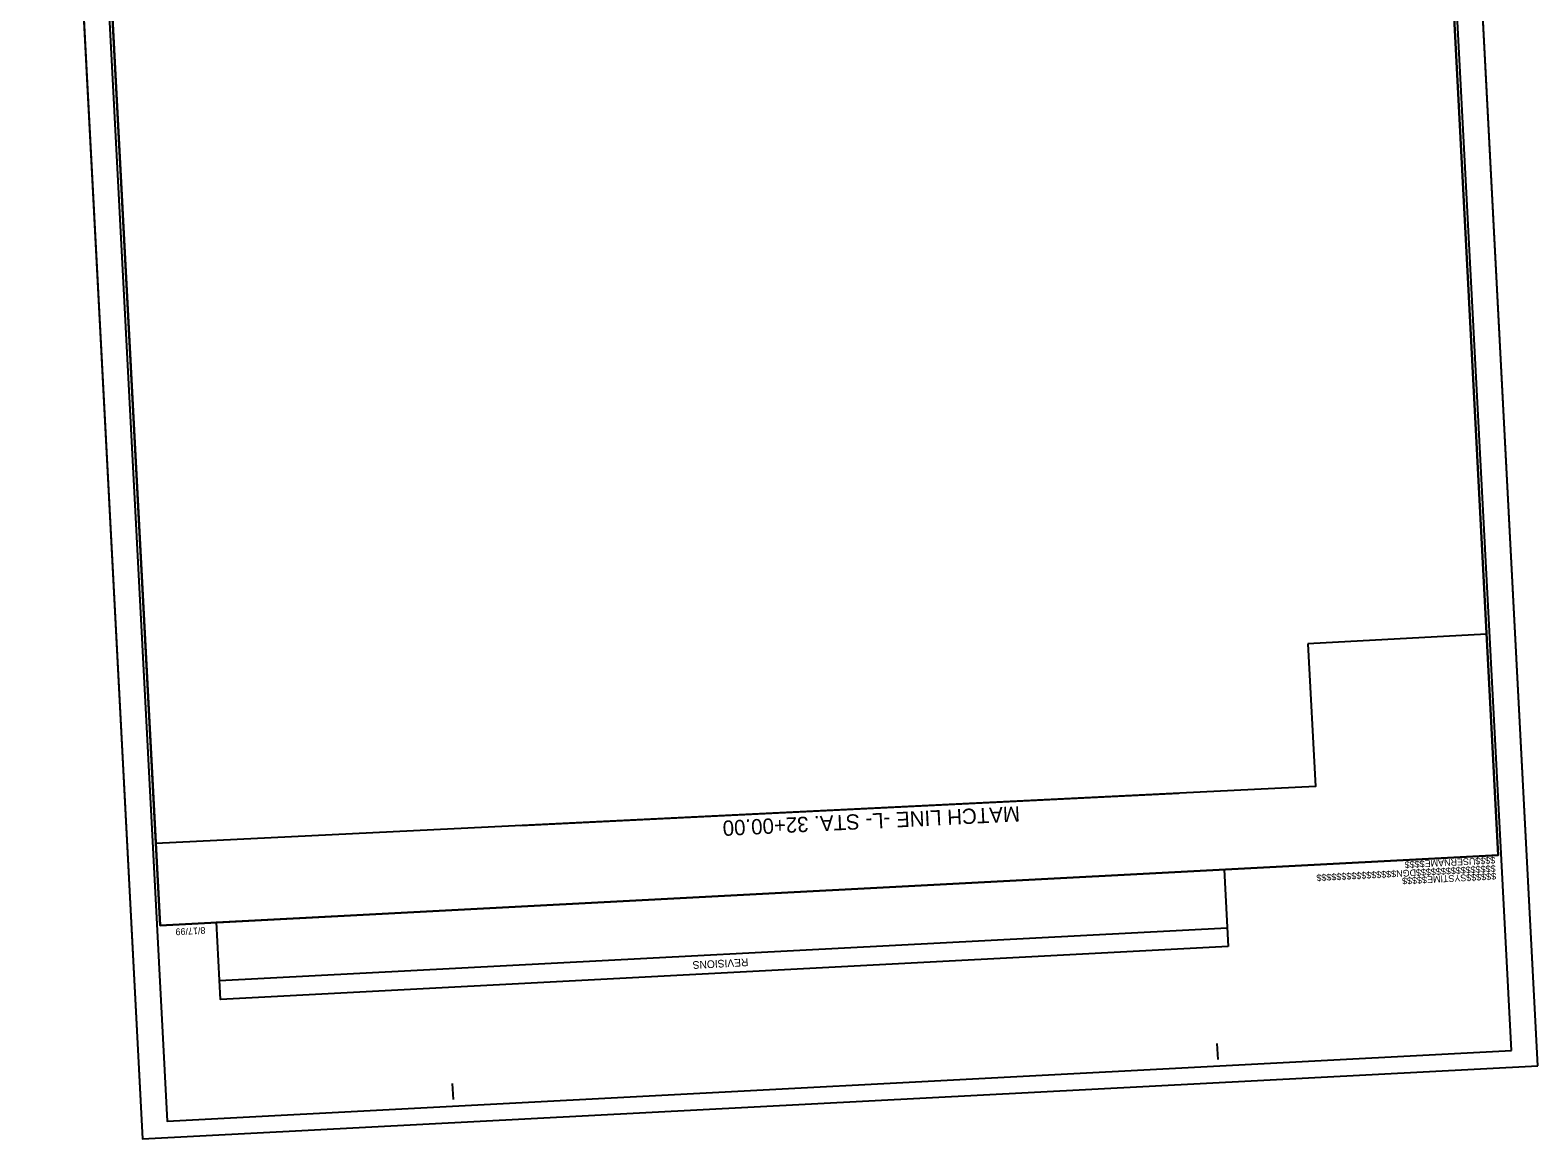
# Model space of a CAD drawing. Extents: x 2368224 to 2369406, y 803271 to 805009.
# Drawn here: x 2368224 to 2369406, y 803271 to 804140 of the extents above; entities that cross this region are included whole.
import ezdxf

# ---------------------------------------------------------------- set-up
doc = ezdxf.new("R2010")
doc.units = 0
for name, color, linetype in [('Old_Level_10', 7, 'Continuous'), ('Old_Level_15', 7, 'Continuous'), ('Old_Level_18', 7, 'Continuous'), ('Old_Level_4', 7, 'Continuous'), ('Old_Level_6', 7, 'Continuous'), ('Old_Level_61', 7, 'Continuous'), ('Old_Level_62', 7, 'Continuous'), ('Plot Shape CELL', 7, 'Continuous'), ('User Information Notes CELL', 7, 'Continuous')]:
    doc.layers.add(name, color=color, linetype=linetype)

msp = doc.modelspace()

# ---------------------------------------------------------------- linework, layer by layer
at = {"layer": 'Old_Level_10'}
msp.add_lwpolyline([(2368326.1, 803438.2), (2369374.6, 803493.2), (2369296.1, 804991.1), (2368458.8, 804947.3), (2368471.3, 804708.3), (2368260.1, 804697.3)], close=True, dxfattribs=at)
at = {"layer": 'Old_Level_15'}
for p, q in [((2369405.8, 803328.1), (2369317.7, 805009.3)), ((2368224.2, 804952), (2368312.3, 803270.8)), ((2368312.3, 803270.8), (2369405.8, 803328.1))]:
    msp.add_line(p, q, dxfattribs=at)
at = {"layer": 'Old_Level_18'}
for points in [[(2369225.6, 803658.8), (2369231.4, 803547.1), (2368322.7, 803502.4), (2368260.1, 804697.3), (2368471.3, 804708.3), (2368463.9, 804849), (2369156, 804909.3), (2369192.5, 804949.8), (2369298, 804955.5), (2369365.5, 803666.4)], [(2369225.6, 803658.8), (2369231.4, 803547.1), (2368322.7, 803502.4), (2368260.1, 804697.3), (2368471.3, 804708.3), (2368463.9, 804849), (2369156, 804909.3), (2369183.1, 804698), (2369311, 804706.5), (2369365.5, 803666.4)]]:
    msp.add_lwpolyline(points, close=True, dxfattribs=at)
at = {"layer": 'Old_Level_4'}
msp.add_lwpolyline([(2369385.1, 803340), (2369298, 805003.7), (2368244.4, 804948.6), (2368331.6, 803284.8)], close=True, dxfattribs=at)
at = {"layer": 'Old_Level_6'}
msp.add_lwpolyline([(2369405.8, 803328.1), (2369317.7, 805009.3), (2368224.2, 804952), (2368312.3, 803270.8)], close=True, dxfattribs=at)
at = {"layer": 'Old_Level_62'}
msp.add_line((2368608.7, 803516.5), (2369124.5, 803541.9), dxfattribs=at)
at = {"layer": 'Plot Shape CELL'}
for p, q in [((2369374.6, 803493.2), (2369374.6, 803493.2)), ((2368326, 803438.3), (2368326, 803438.3)), ((2369155.2, 803333), (2369154.5, 803345.5)), ((2368556, 803301.6), (2368555.3, 803314.1))]:
    msp.add_line(p, q, dxfattribs=at)
for points in [[(2368247.6, 804936.2), (2368326, 803438.3), (2369374.6, 803493.2), (2369296.1, 804991.1)], [(2369374.6, 803493.2), (2368326.1, 803438.2), (2368258, 804736.4), (2368407.9, 804744.3), (2368397.4, 804944.1), (2369296.1, 804991.1)]]:
    msp.add_lwpolyline(points, close=True, dxfattribs=at)
at = {"layer": 'User Information Notes CELL'}
msp.add_line((2369162.3, 803436), (2368372.7, 803394.6), dxfattribs=at)
msp.add_lwpolyline([(2369163.1, 803421.5), (2368373.5, 803380.1), (2368370.3, 803440.6), (2369159.9, 803481.9)], close=True, dxfattribs=at)

# ---------------------------------------------------------------- texts
at = {"layer": 'Old_Level_61'}
msp.add_text('MATCH LINE -L- STA. 32+00.00', height=12, rotation=182.8145, dxfattribs=at).set_placement((2368999.6, 803531.7))
at = {"layer": 'Plot Shape CELL'}
for s, p in [('$$$$USERNAME$$$$', (2369372.3, 803492)), ('$$$$$$$$$$$$$$$$DGN$$$$$$$$$$$$$$$$', (2369372.6, 803485.4)), ('$$$$$$SYSTIME$$$$$', (2369373, 803479.4)), ('8/17/99', (2368361.4, 803436.9))]:
    msp.add_text(s, height=5.25, rotation=182.9979, dxfattribs=at).set_placement(p)
at = {"layer": 'User Information Notes CELL'}
msp.add_text('REVISIONS', height=6, rotation=182.9979, dxfattribs=at).set_placement((2368786.9, 803412.3))

doc.saveas('drawing.dxf')
